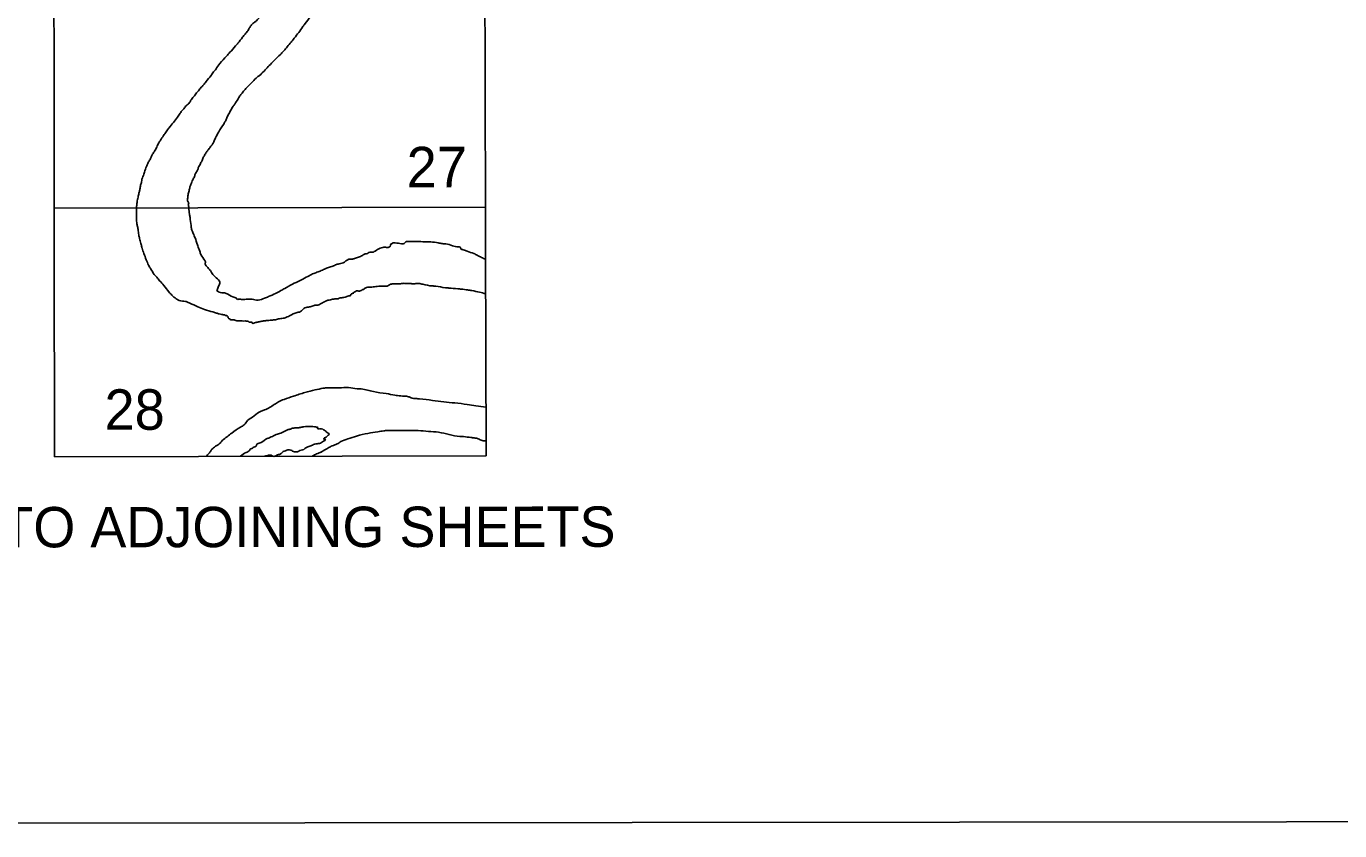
# Model space of a CAD drawing. Extents: x 3297735 to 3335592, y 670436 to 695807.
# Drawn here: x 3322973 to 3326767, y 671647 to 673973 of the extents above; entities that cross this region are included whole.
import ezdxf

# ---------------------------------------------------------------- set-up
doc = ezdxf.new("R2010")
doc.units = 0
doc.layers.add('V-ANNO-NPLT', color=7, linetype='Continuous')
doc.layers.add('V-ANNO-SYMB', color=7, linetype='Continuous')

msp = doc.modelspace()

# ---------------------------------------------------------------- linework, layer by layer
at = {"layer": 'V-ANNO-NPLT'}
msp.add_line((3323469.9, 673334.4), (3323474.2, 673322.2), dxfattribs=at)
for points in [[(3324298.5, 673775.8), (3324297.5, 674167.6), (3323052.5, 674165.1), (3323053.1, 673774.5)], [(3323053.1, 673774.5), (3323053.6, 673446.8)], [(3323053.6, 673446.8), (3324299.3, 673449.4), (3324298.5, 673775.8)], [(3324299.6, 673335.3), (3324299.3, 673449.4), (3323053.6, 673446.8), (3323053.8, 673334)], [(3323053.8, 673334), (3323054.8, 672728.6)], [(3323054.8, 672728.6), (3324301.1, 672731.2), (3324299.6, 673335.3)]]:
    msp.add_lwpolyline(points, dxfattribs=at)
for points in [[(3323620.4, 673972.7), (3323627.5, 673980.2), (3323632.6, 673984.2), (3323638.6, 673989.7), (3323646.4, 673998.4), (3323657.5, 674013.1), (3323662.2, 674019.8), (3323676.4, 674036.8), (3323682.7, 674046.3), (3323688.6, 674053.4)], [(3323747.1, 673938.5), (3323759.8, 673954.7), (3323771.6, 673971.7), (3323778.3, 673980.4), (3323793.3, 674001.3), (3323798.8, 674011.2), (3323805.1, 674022.3), (3323809.8, 674029), (3323814.1, 674036.5), (3323820.4, 674050), (3323822, 674054.3)], [(3323521.1, 673849.3), (3323532.1, 673865.2), (3323551.4, 673886.5), (3323561.3, 673897.6), (3323577.5, 673915.8), (3323584.2, 673923.7), (3323597.6, 673941.1), (3323601.5, 673945.8), (3323609, 673954.5), (3323616.1, 673965.2), (3323620.4, 673972.7)], [(3323647, 673830.5), (3323659.6, 673843.2), (3323671.8, 673856.2), (3323684.5, 673868.9), (3323695.5, 673880.3), (3323709.3, 673893.4), (3323717.2, 673901.7), (3323726.6, 673913.6), (3323738.1, 673927), (3323747.1, 673938.5)], [(3323462.6, 673777.8), (3323470.2, 673786.5), (3323478.5, 673796.3), (3323484.4, 673803.1), (3323492.3, 673813), (3323506.5, 673830), (3323514, 673840.6), (3323521.1, 673849.3)], [(3323590, 673771.2), (3323596.1, 673779.5), (3323604.8, 673789.8), (3323615.9, 673801.6), (3323626.9, 673812.7), (3323640.3, 673825.8), (3323647, 673830.5)], [(3323360.5, 673643.3), (3323369.5, 673656.8), (3323377, 673667.4), (3323384.9, 673678.5), (3323397.9, 673694.3), (3323409.3, 673710.1), (3323417.6, 673721.2), (3323420.8, 673726), (3323427.9, 673733.9), (3323435.4, 673744.1), (3323440.5, 673747.7), (3323447.6, 673757.2), (3323449.9, 673761.2), (3323458.6, 673771.8), (3323462.6, 673777.8)], [(3323519.5, 673649.8), (3323529, 673668), (3323543.2, 673690.1), (3323547.9, 673698.4), (3323551.8, 673707.9), (3323558.1, 673719.8), (3323563.6, 673729.7), (3323570.7, 673741.5), (3323573.5, 673745.5), (3323579, 673753.8), (3323590, 673771.2)], [(3323323.6, 673576.1), (3323329, 673585.6), (3323334.1, 673594.7), (3323338, 673603), (3323343.5, 673612.1), (3323349.8, 673623.6), (3323355.7, 673635.8), (3323360.5, 673643.3)], [(3323477.6, 673578.6), (3323481.7, 673587.3), (3323484.1, 673593.7), (3323486.4, 673597.2), (3323491.9, 673606.7), (3323497.8, 673614.2), (3323504.5, 673623.7), (3323508.5, 673628.9), (3323513.2, 673635.2), (3323514.4, 673638.7), (3323519.5, 673649.8)], [(3323291.3, 673447.3), (3323292.2, 673457.5), (3323293.7, 673468.6), (3323296.5, 673482), (3323298.9, 673492.7), (3323301.2, 673501.8), (3323303.2, 673513.3), (3323305.9, 673523.5), (3323307.1, 673531.1), (3323309.9, 673538.6), (3323314.2, 673551.2), (3323320.1, 673567.4), (3323323.6, 673576.1)], [(3323442.5, 673447.6), (3323441.8, 673453), (3323441, 673457.7), (3323442.2, 673462), (3323441.4, 673463.6), (3323439.4, 673466), (3323438.6, 673470.7), (3323439.4, 673477.1), (3323439.8, 673482.2), (3323440.9, 673488.1), (3323442.5, 673493.7), (3323443.7, 673500), (3323444.9, 673504.7), (3323445.7, 673508.3), (3323447.2, 673512.6), (3323449.2, 673517.4), (3323450.8, 673522.1), (3323453.9, 673528.8), (3323456.3, 673533.6), (3323458.7, 673538.3), (3323460.2, 673543.1), (3323464.6, 673551.8), (3323468.1, 673558.9), (3323471.6, 673567.2), (3323474.8, 673573.1), (3323477.6, 673578.6)], [(3323291.4, 673447.3), (3323291.4, 673418.5), (3323291.8, 673405.8), (3323293.7, 673396.8), (3323295.7, 673384.8), (3323298, 673369.7), (3323300.3, 673359.2), (3323304.2, 673344.9), (3323306.6, 673334.3)], [(3323442.5, 673447.6), (3323444.3, 673429.9), (3323445.9, 673419.9), (3323449, 673396.6), (3323450.6, 673386.1), (3323455.2, 673373.4), (3323460.3, 673361.3), (3323467.6, 673340.8), (3323469.9, 673334.4)], [(3323306.6, 673334.3), (3323307.3, 673331), (3323312.8, 673315.5)], [(3324021.3, 673335), (3324018.6, 673333.6), (3324013.4, 673333.6), (3324002.7, 673333.6), (3323994.7, 673331.2), (3323980.7, 673322.8), (3323975.5, 673320), (3323970.4, 673319.5), (3323962.4, 673319), (3323959.1, 673316.2), (3323952.1, 673314.8), (3323944.2, 673310.6), (3323932.9, 673304.9), (3323921.2, 673301.6), (3323912.8, 673299.3), (3323902.5, 673298.3), (3323900.2, 673296.5), (3323896.4, 673295), (3323891.7, 673290.8), (3323876.8, 673286.1), (3323866, 673282.8)], [(3324066.8, 673346.8), (3324061.6, 673343.5), (3324057, 673343.9), (3324038.7, 673346.3), (3324032.6, 673346.3), (3324029.3, 673344.9), (3324026.1, 673343), (3324024.2, 673336.4), (3324021.3, 673335)], [(3324216.7, 673335.2), (3324216.6, 673335.2), (3324199.7, 673339.9), (3324180.1, 673344.1), (3324174, 673344.5), (3324162.8, 673346.9), (3324141.2, 673349.2), (3324129.5, 673349.2), (3324107, 673350.6), (3324097.7, 673350.6), (3324071.9, 673351), (3324071.5, 673351), (3324066.8, 673346.8)], [(3324299.7, 673299.4), (3324287.8, 673304.3), (3324275.6, 673310.9), (3324265.8, 673315.6), (3324246.6, 673322.6), (3324235.3, 673326.8), (3324227.8, 673330.1), (3324227.4, 673331.9), (3324216.7, 673335.2)], [(3323312.8, 673315.5), (3323319.4, 673298), (3323326.4, 673281.7), (3323332.2, 673272.1), (3323342.7, 673255.4), (3323349.6, 673247.7)], [(3323474.2, 673322.2), (3323477.3, 673312.9), (3323489, 673295.5), (3323490.5, 673291.6), (3323490.1, 673287.7), (3323490.5, 673282.7), (3323495.2, 673277.7), (3323499.1, 673273), (3323504.9, 673266.4)], [(3323504.9, 673266.4), (3323521.2, 673245.5), (3323532, 673232.7), (3323530.9, 673227.3), (3323528.5, 673221.9), (3323525.8, 673215.3), (3323524.7, 673211), (3323523.3, 673207)], [(3323866, 673282.8), (3323855.2, 673278.1), (3323848.7, 673276.6), (3323837.9, 673272.4), (3323824.8, 673266.3), (3323812.6, 673261.6), (3323800, 673256.9), (3323786.4, 673249.9), (3323766.3, 673239.1), (3323757.9, 673234.8), (3323736.4, 673224.5), (3323726.5, 673218.9), (3323719.5, 673215.1)], [(3323349.6, 673247.7), (3323358.2, 673237.2), (3323370.6, 673223.3), (3323384.5, 673205.1), (3323393.4, 673195.8), (3323406.2, 673184.9), (3323414.8, 673179.9), (3323423.7, 673178.3), (3323432.6, 673177.6), (3323440.3, 673174.1), (3323445.7, 673172.2)], [(3323719.5, 673215.1), (3323707.8, 673208.5), (3323692.9, 673200.6), (3323672.7, 673191.2), (3323661, 673186.5), (3323642.8, 673181.3), (3323633.4, 673182.2), (3323625.5, 673183.6), (3323616.1, 673184.1), (3323608.6, 673184.1), (3323599.7, 673182.7), (3323588.9, 673183.6), (3323580.5, 673185), (3323580, 673186.4), (3323574.9, 673189.2), (3323555.2, 673198.1), (3323545.8, 673202.3), (3323537.9, 673202.3), (3323529.9, 673204.1), (3323523.4, 673207), (3323523.3, 673207)], [(3324066.8, 673229.6), (3324061.3, 673229.6), (3324051.5, 673228.2), (3324042.1, 673228.2), (3324032.7, 673228.2), (3324027.6, 673227.7), (3324022, 673225.8), (3324020.1, 673223.9), (3324014.9, 673221.6), (3324002.3, 673221.6), (3323991.5, 673221.1), (3323982.2, 673220.1), (3323974.7, 673219.2), (3323967.7, 673218.7), (3323959.2, 673218.7), (3323951.7, 673215.9), (3323949.4, 673214.5), (3323948.9, 673212.6), (3323945.7, 673211.7), (3323943.8, 673211.7), (3323941.9, 673210.3), (3323933, 673207.4), (3323929.3, 673208.4), (3323923.7, 673206.5), (3323916.6, 673200.9)], [(3324299.9, 673199.5), (3324282.3, 673204), (3324259.8, 673208.7), (3324247.6, 673210.6), (3324229.8, 673212.9), (3324219.1, 673213.8), (3324193.8, 673216.1), (3324183.5, 673217.1), (3324155.9, 673221.3), (3324145.1, 673222.2), (3324118.4, 673226.8), (3324107.2, 673229.2), (3324095.5, 673228.7), (3324087, 673228.7), (3324076.7, 673229.1), (3324066, 673229.6)], [(3323917.7, 673201.7), (3323909.6, 673195.2), (3323909.2, 673193.8), (3323907.3, 673193.7), (3323896.5, 673190.5), (3323884.4, 673188.1), (3323879.7, 673187.6), (3323874.1, 673185.3), (3323864.2, 673184.8), (3323851.6, 673182), (3323843.6, 673180.6), (3323837.1, 673177.7), (3323831.5, 673174.9), (3323824.9, 673171.6), (3323819.8, 673168.4), (3323815.1, 673166.5), (3323812.3, 673166.9), (3323801.5, 673164.6), (3323795.9, 673162.7), (3323790.7, 673161.3), (3323784.7, 673160.8), (3323777.6, 673158.5), (3323771.6, 673154.2), (3323767.8, 673150), (3323761.7, 673146.7), (3323755.6, 673145.3), (3323733.2, 673135.5)], [(3323445.7, 673172.2), (3323468.2, 673162.1), (3323487.6, 673154.4), (3323512.2, 673146.9)], [(3323733.2, 673135.5), (3323726.6, 673132.6), (3323718.2, 673129.3), (3323704.6, 673127.5), (3323692.5, 673124.6), (3323681.7, 673123.2), (3323666.2, 673121.8), (3323656, 673120.4), (3323650.8, 673119.4), (3323641.4, 673117.5), (3323632.5, 673115.2), (3323626, 673114.3), (3323624.6, 673117.1), (3323622.2, 673117.5), (3323620.8, 673117.1), (3323612.4, 673119.9), (3323608.2, 673120.8), (3323601.2, 673120.8), (3323591.3, 673121.2), (3323581.5, 673121.2), (3323575.4, 673123.1), (3323570.3, 673124.5), (3323562.8, 673124.5), (3323560.9, 673126.8), (3323557.6, 673127.8), (3323555.7, 673132.5), (3323548.7, 673137.1), (3323541.7, 673139), (3323537.5, 673139.5), (3323530.5, 673141.3), (3323522, 673143.7), (3323512.2, 673146.9)], [(3324012.6, 672911.1), (3323975.9, 672916.6), (3323940.5, 672924.5), (3323928.3, 672925.1), (3323903.8, 672928.2), (3323876.9, 672927.5), (3323864.1, 672927.5), (3323839.6, 672927.5), (3323829.9, 672926.2), (3323807.3, 672921.9), (3323777.9, 672914), (3323744.9, 672903.5), (3323717.4, 672894.3)], [(3324300.7, 672871.7), (3324271.8, 672875.9), (3324246.7, 672879.6), (3324210.6, 672883.8), (3324178.9, 672886.8), (3324145.9, 672891.1), (3324109.2, 672895.9), (3324098.2, 672896.5), (3324084.7, 672898.4), (3324077.4, 672902), (3324065.2, 672903.8), (3324045, 672905), (3324037.7, 672906.3), (3324012.6, 672911.1)], [(3323717.4, 672894.3), (3323701.6, 672886.9), (3323689.4, 672879.5), (3323661.3, 672863.6), (3323651.5, 672860.5), (3323630.7, 672846.4), (3323612.4, 672833), (3323602, 672820.7), (3323591.6, 672814), (3323566.6, 672796.8), (3323539.7, 672776)], [(3323662.2, 672730.2), (3323667.7, 672731.5), (3323673, 672732.6), (3323678.4, 672732.6), (3323681.6, 672732.6), (3323685.4, 672729.9), (3323691.3, 672729.9), (3323696.7, 672733.1), (3323706.3, 672735.8), (3323709, 672737.4), (3323710.6, 672739), (3323714.9, 672743.4), (3323721.4, 672746), (3323728.9, 672748.2), (3323733.2, 672748.2), (3323740.2, 672746.1), (3323744.5, 672743.9), (3323750.9, 672742.3), (3323756.3, 672742.9), (3323763.2, 672746.1), (3323770.8, 672748.2), (3323784.2, 672756.3), (3323794.4, 672760.1), (3323805.1, 672764.4), (3323813.2, 672766), (3323822.3, 672767.7), (3323831.4, 672773.6), (3323836.8, 672777.9), (3323834.6, 672779.5), (3323832, 672779.5), (3323832.5, 672781.6), (3323836.8, 672783.8), (3323841.1, 672786.5), (3323845.4, 672790.8), (3323847.5, 672793.5), (3323844.8, 672796.7), (3323839.5, 672800.5), (3323831.9, 672806.4), (3323820.1, 672809.6), (3323817.4, 672809.6), (3323813.7, 672810.1), (3323814.7, 672813.4), (3323811.5, 672814.4), (3323805.1, 672815), (3323795.9, 672816), (3323790.6, 672816), (3323783.6, 672816), (3323774.5, 672814.9), (3323764.8, 672813.3), (3323760, 672812.2), (3323751.9, 672812.2), (3323745.5, 672811.1)], [(3323745.5, 672811.1), (3323740.6, 672810.6), (3323735.8, 672808.4), (3323732, 672807.4), (3323723.4, 672804.1), (3323715.9, 672800.3), (3323707.9, 672796.6), (3323701.4, 672794.4), (3323695, 672792.3), (3323687.5, 672788.5), (3323680, 672785.8), (3323673.5, 672782.6)], [(3323824.6, 672742.1), (3323846.5, 672754.9), (3323856.3, 672759.9), (3323871, 672765.4), (3323881.4, 672772.1), (3323902.1, 672780.1), (3323927.2, 672788.1), (3323959.6, 672796.1), (3323988.3, 672800.4), (3324005.4, 672803.4), (3324015.8, 672804.1)], [(3324015.8, 672804.1), (3324045.7, 672804.1), (3324076.9, 672804.7), (3324105, 672804.2), (3324134.3, 672801.7), (3324163.7, 672799.3), (3324194.2, 672792.6), (3324225.4, 672787.2), (3324235.8, 672786.5), (3324257.2, 672784.1), (3324267, 672782.9), (3324278.6, 672780.5), (3324290.2, 672775), (3324295.7, 672774.4), (3324301, 672774.4)], [(3323539.7, 672776), (3323530, 672765.6), (3323516.5, 672756.4), (3323511.6, 672752.7), (3323506.1, 672746), (3323500.7, 672738), (3323492.2, 672729.5)], [(3323673.5, 672782.6), (3323664.9, 672778.8), (3323646.1, 672767.5), (3323639.7, 672765.3), (3323638.1, 672762.1), (3323637.6, 672760.5), (3323636.5, 672758.9), (3323632.7, 672757.2), (3323624.1, 672752.4), (3323619.3, 672750.2), (3323618.2, 672748.1), (3323616.6, 672745.9), (3323613.9, 672743.3), (3323608, 672741.1), (3323591.4, 672730.3), (3323590.3, 672729.9)], [(3323825.7, 672742.7), (3323811.7, 672736.5), (3323799.5, 672731)]]:
    msp.add_spline(points, degree=3, dxfattribs=at)
at = {"layer": 'V-ANNO-SYMB'}
msp.add_lwpolyline([(3301092, 671647.5), (3334175.2, 671681.1), (3334151.9, 694597.7), (3301068.7, 694564), (3301092, 671647.5)], dxfattribs=at)

# ---------------------------------------------------------------- texts
at = {"layer": 'V-ANNO-NPLT'}
for s, height, p in [('27', 117, (3324071.8, 673507.2)), ('28', 117, (3323198.9, 672806.3)), ('INDEX TO ADJOINING SHEETS', 116.66, (3322377.9, 672465.9))]:
    msp.add_text(s, height=height, rotation=0.0583, dxfattribs=at).set_placement(p)

doc.saveas('drawing.dxf')
